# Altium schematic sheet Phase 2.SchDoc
size Tabloid; SheetNumber: 4; SheetTotal: 7
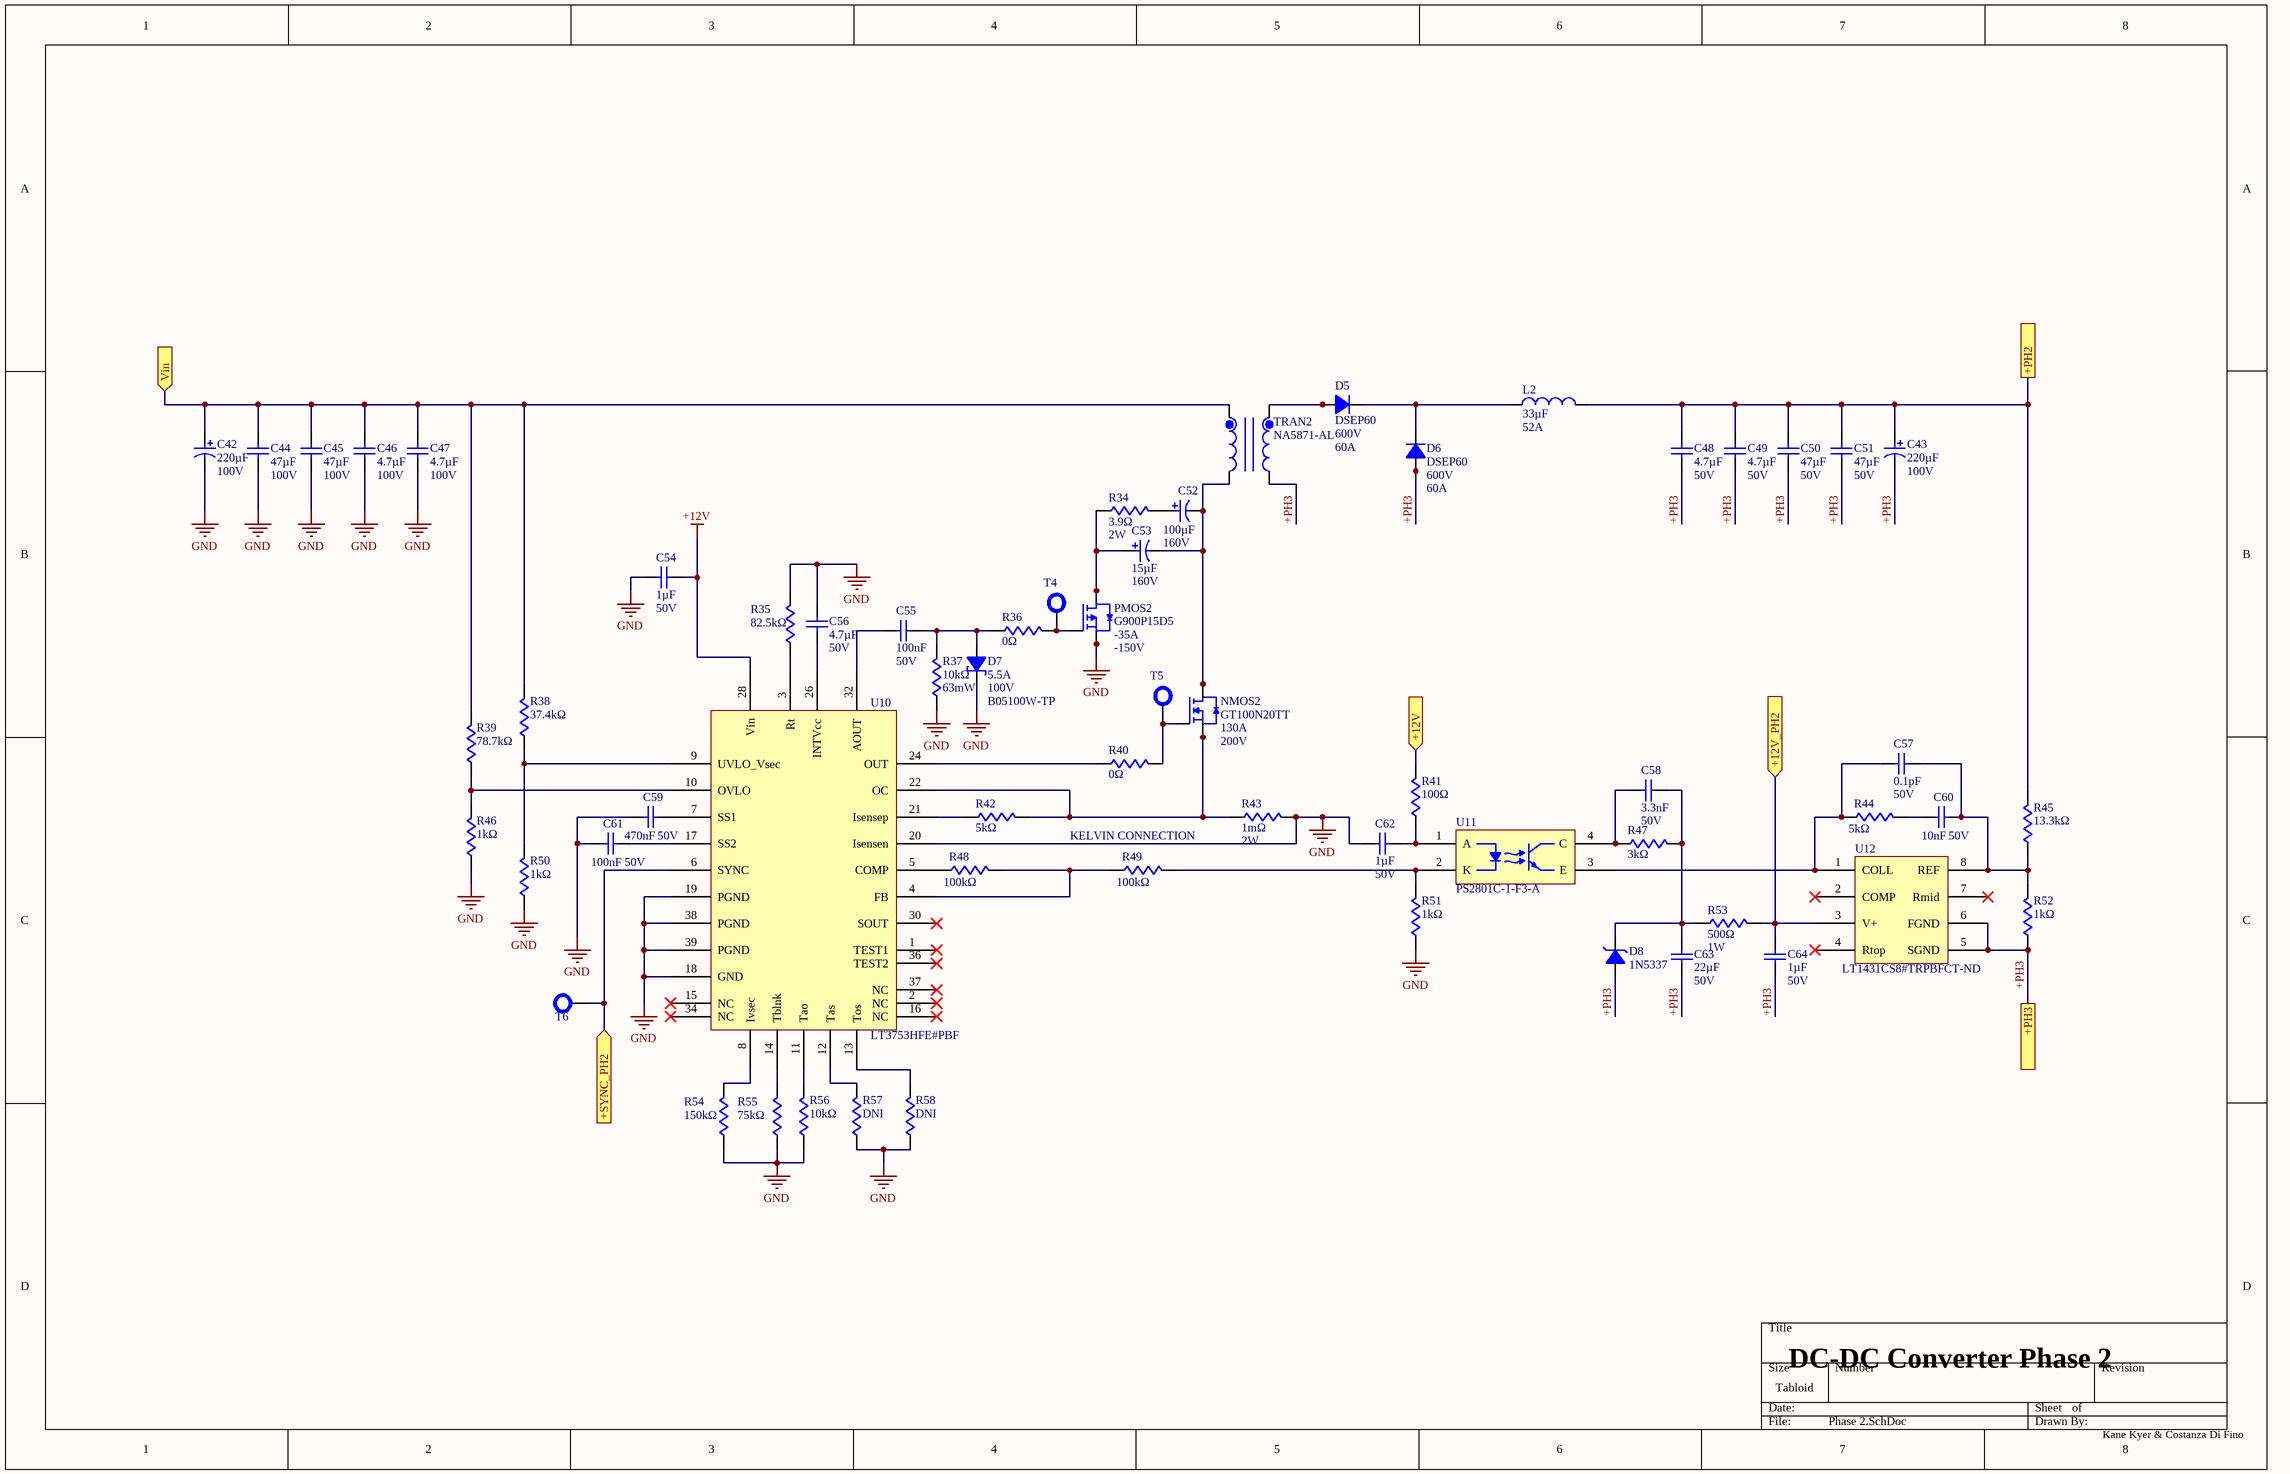
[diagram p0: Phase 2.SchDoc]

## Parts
C42  value 220µF  Voltage Rating: 100V  [C_AEC]  (hidden comment: AFK227M2AR44T-F)
C43  value 220µF  Voltage Rating: 100V  [C_AEC]  (hidden comment: AFK227M2AR44T-F)
C44  value 47µF  Voltage Rating: 100V  [C_CAA573]  (hidden comment: CAA573X7S2A476M640LH)
C45  value 47µF  Voltage Rating: 100V  [C_CAA573]  (hidden comment: CAA573X7S2A476M640LH)
C46  value 4.7µF  Voltage Rating (DC): 100V  [C_1210]  (hidden comment: GMC32X7S475K100NT)
C47  value 4.7µF  Voltage Rating (DC): 100V  [C_1210]  (hidden comment: GMC32X7S475K100NT)
C48  value 4.7µF  Voltage Rating (DC): 50V  [C_1206]  (hidden comment: GMC31X7R475K50NT)
C49  value 4.7µF  Voltage Rating (DC): 50V  [C_1206]  (hidden comment: GMC31X7R475K50NT)
C50  value 47µF  Voltage Rating (DC): 50V  [C_CKG57N]  (hidden comment: CKG57NX7R1H476M500JJ)
C51  value 47µF  Voltage Rating (DC): 50V  [C_CKG57N]  (hidden comment: CKG57NX7R1H476M500JJ)
C52  value 100µF  Voltage Rating (DC): 160V  [UUJ2C101MNJ1MS]  (hidden comment: UUJ2C101MNJ1MS)
C53  value 15µF  Voltage: 160V  [ULT2C150MNL1GS]  (hidden comment: ULT2C150MNL1GS)
C54  value 1µF  Voltage: 50V  [C_0805]  (hidden comment: CL21B105KBFNNNE)
C55  value 100nF  Voltage Rating: 50V  [C_0603]  (hidden comment: C0603C104K5RACTU)
C56  value 4.7µF  Voltage Rating (DC): 50V  [C_1206]  (hidden comment: GMC31X7R475K50NT)
C57  value 0.1pF  Voltage Rating: 50V  [C_0402]  (hidden comment: GJM1555C1HR10WB01D)
C58  value 3.3nF  Voltage Rating: 50V  [C_0603]  (hidden comment: GCM1885C1H332FA16D)
C59  value 470nF  Voltage Rating: 50V  [C_0402]  (hidden comment: GRM155R61H474KE11D)
C60  value 10nF  Voltage Rating: 50V  [C_0603]  (hidden comment: C0603C103K5RACTU)
C61  value 100nF  Voltage Rating: 50V  [C_0603]  (hidden comment: C0603C104K5RACTU)
C62  value 1µF  Voltage: 50V  [C_0805]  (hidden comment: CL21B105KBFNNNE)
C63  value 22µF  Voltage Rating (DC): 50V  [C_2220]  (hidden comment: GMC55X7R226M50NT)
C64  value 1µF  Voltage: 50V  [C_0805]  (hidden comment: CL21B105KBFNNNE)
D5  DSEP60  Vr: 600V  Io: 60A  [D_DSEP60]
D6  DSEP60  Vr: 600V  Io: 60A  [D_DSEP60]
D7  Max Forward Surge Current (Ifsm): 5.5A  Min Breakdown Voltage: 100V  [D_B05100W]  (hidden comment: B05100W-TP)
D8  Supplier Part Number: 1N5337  [D_1N5337]  (hidden comment: 1N5337BRLG)
L2  value 33µF  Irms: 52A  [CPEX4141L-330MC]  (hidden comment: CPEX4141L-330MC)
NMOS2  Id: 130A  Vds: 200V  [GT100N20TT]  (hidden comment: GT100N20TT)
PMOS2  Id: -35A  Vds: -150V  [G900P15]  (hidden comment: G900P15D5)
R34  value 3.9Ω  Power Rating: 2W  [R_SM2W]  (hidden comment: SMW23R9JT)
R35  value 82.5kΩ  [R_0805]  (hidden comment: RMCF0805FT82K5)
R36  value 0Ω  [R_0805]  (hidden comment: CRCW08050000Z0EA)
R37  value 10kΩ  Power Rating: 63mW  [R_0402]  (hidden comment: RM04F1002CT)
R38  value 37.4kΩ  [R_0603]  (hidden comment: RC0603FR-0737K4L)
R39  value 78.7kΩ  [R_0603]  (hidden comment: RC0603FR-0778K7L)
R40  value 0Ω  [R_0805]  (hidden comment: CRCW08050000Z0EA)
R41  value 100Ω  [R_0603]  (hidden comment: RC0603FR-07100RL)
R42  value 5kΩ  [R_0402]  (hidden comment: PNM0402E5001BST1)
R43  value 1mΩ  Power Rating: 2W  [R_2512]  (hidden comment: CRE2512-FZ-R001E-2)
R44  value 5kΩ  [R_0402]  (hidden comment: PNM0402E5001BST1)
R45  value 13.3kΩ  [R_0603]  (hidden comment: RMCF0603FT13K3)
R46  value 1kΩ  [R_0402]  (hidden comment: RM04F1001CT)
R47  value 3kΩ  [C_0402]  (hidden comment: AC0402FR-073KL)
R48  value 100kΩ  [R_0402]  (hidden comment: RM04F1003CT)
R49  value 100kΩ  [R_0402]  (hidden comment: RM04F1003CT)
R50  value 1kΩ  [R_0402]  (hidden comment: RM04F1001CT)
R51  value 1kΩ  [R_0402]  (hidden comment: RM04F1001CT)
R52  value 1kΩ  [R_0402]  (hidden comment: RM04F1001CT)
R53  value 500Ω  Power Rating: 1W  [R_WSC2515]  (hidden comment: WSC2515500R0FEB)
R54  value 150kΩ  [R_0603]  (hidden comment: RC0603FR-07150KL)
R55  value 75kΩ  [R_0603]  (hidden comment: AC0603FR-0775KL)
R56  value 10kΩ  [R_0402]  (hidden comment: RM04F1002CT)
R57  value DNI  [R_0805]  (hidden comment: CRCW08050000Z0EA)
R58  value DNI  [R_0805]  (hidden comment: CRCW08050000Z0EA)
T4  TEST  [TEST_POINT]  (value not drawn)
T5  TEST  [TEST_POINT]  (value not drawn)
T6  TEST  [TEST_POINT]  (value not drawn)
TRAN2  NA5871-AL  [NA5871-AL]
U10  LT3753HFE#PBF  [LT3753]
U11  PS2801C-1-F3-A  [PS2801C]
U12  Supplier Part Number: LT1431CS8#TRPBFCT-ND  [LT1431]  (hidden comment: LT1431CS8#TRPBF)

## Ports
+12V (in, see SHEET_MAP[4B], Externals[2A], Phase 1[4C], Phase 3[4C], Phase 4[4C], Phase 5[4B]), +12V_PH2 (in, see SHEET_MAP[4B], Externals[5B]), +PH2 (see SHEET_MAP[4B], Externals[4B], Phase 1[6C]), +PH3 (see SHEET_MAP[4B], Externals[4C], Phase 3[6B]), +SYNC_PH2 (in, see SHEET_MAP[4B], Externals[3C]), Vin (in, see SHEET_MAP[4B], Externals[1A], Phase 1[1B], Phase 3[1B], Phase 4[1B], Phase 5[1B])

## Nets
+12V: C54.2 U10.28(Vin)
GND: C42.2 C44.1 C45.1 C46.1 C47.1 C54.1 C56.1 C59.1 C61.1 C62.1 D7.1 PMOS2.1(S) PMOS2.2(S) PMOS2.3(S) R35.2 R37.1 R43.2 R46.1 R50.1 R51.1 R54.1 R55.1 R56.1 R57.1 R58.1 U10.18(GND) U10.19(PGND) U10.20(Isensen) U10.38(PGND) U10.39(PGND)
+12V: R41.2 ; port +12V  [a separate net that carries the same name]
+12V_PH2: C64.2 R53.2 U12.3(V+) ; port +12V_PH2
+PH2: C43.1 C48.2 C49.2 C50.2 C51.2 L2.2 R45.2 ; port +PH2
+PH3: C43.2 C48.1 C49.1 C50.1 C51.1 C63.1 C64.1 D6.1(A) D6.3(A) D8.2 R52.1 TRAN2.11 U12.5(SGND) U12.6(FGND) ; port +PH3
+SYNC_PH2: T6.1 U10.6(SYNC) ; port +SYNC_PH2
Vin: C42.1 C44.2 C45.2 C46.2 C47.2 R38.2 R39.2 TRAN2.1 ; port Vin
NetC52_1: C52.1 R34.2
NetC52_2: C52.2 C53.2 NMOS2.9(D) NMOS2.10(D) NMOS2.11(D) NMOS2.12(D) NMOS2.13(D) NMOS2.14(D) NMOS2.15(D) NMOS2.16(D) TRAN2.4
NetC53_1: C53.1 PMOS2.5(D) PMOS2.6(D) PMOS2.7(D) PMOS2.8(D) R34.1
NetC55_1: C55.1 U10.32(AOUT)
NetC55_2: C55.2 D7.2 R36.1 R37.2
NetC56_2: C56.2 U10.26(INTVcc)
NetC57_1: C57.1 R44.1 U11.3(E) U12.1(COLL)
NetC57_2: C57.2 C60.2 R45.1 R52.2 U12.8(REF)
NetC58_1: C58.1 R47.1 U11.4(C)
NetC58_2: C58.2 C63.2 D8.1 R47.2 R53.1
NetC59_2: C59.2 U10.7(SS1)
NetC60_1: C60.1 R44.2
NetC61_2: C61.2 U10.17(SS2)
NetC62_2: C62.2 R41.1 U11.1(A)
NetD5_1: D5.1(A) D5.3(A) TRAN2.6
NetD5_4: D5.4(C) D6.4(C) L2.1
NetNMOS2_1: NMOS2.1(S) NMOS2.2(S) NMOS2.3(S) NMOS2.4(S) NMOS2.5(S) NMOS2.6(S) NMOS2.7(S) R42.2 R43.1 U10.22(OC)
NetNMOS2_8: NMOS2.8(G) R40.2 T5.1
NetPMOS2_4: PMOS2.4(G) R36.2 T4.1
NetR35_1: R35.1 U10.3(Rt)
NetR38_1: R38.1 R50.2 U10.9(UVLO_Vsec)
NetR39_1: R39.1 R46.2 U10.10(OVLO)
NetR40_1: R40.1 U10.24(OUT)
NetR42_1: R42.1 U10.21(Isensep)
NetR48_1: R48.1 U10.5(COMP)
NetR48_2: R48.2 R49.1 U10.4(FB)
NetR49_2: R49.2 R51.2 U11.2(K)
NetR54_2: R54.2 U10.8(Ivsec)
NetR55_2: R55.2 U10.14(Tblnk)
NetR56_2: R56.2 U10.11(Tao)
NetR57_2: R57.2 U10.12(Tas)
NetR58_2: R58.2 U10.13(Tos)

Not connected (* = marked no-connect by the designer): U10 1(TEST1)* 2(NC)* 15(NC)* 16(NC)* 30(SOUT)* 34(NC)* 36(TEST2)* 37(NC)*; U12 2(COMP)* 4(Rtop)* 7(Rmid)*

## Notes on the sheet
- (near R49) KELVIN CONNECTION
- DC-DC Converter Phase 2
- Kane Kyer & Costanza Di Fino

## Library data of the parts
C42 C43 = AFK227M2AR44T-F: Radial Can - SMD ALUMINUM ELECTROLYTIC CAPACITOR AFK 100V 220muF ±20% 0.709Dia 18.00mm; Manufacturer: Cornell Dubilier; Dissipation Factor: 0.07%; ESR (Equivalent Series Resistance): 150mΩ; Leakage Current: 220µA; Life (Hours): 5000hours; Ripple Current: 687.75mA; Ripple Current (AC): 917mA
C44 C45 = CAA573X7S2A476M640LH: Multilayer Ceramic Chip Capacitors, Capacitance=47μF, LxWxT: 6.0x7.5x6.4mm; Manufacturer: TDK; Manufacturer Lifecycle Status: PRODUCTION; Tolerance: 20%
C46 C47 = GMC32X7S475K100NT: Ceramic Capacitor, Multilayer, Ceramic, 100V, 10% +Tol, 10% -Tol, X7S, 22% TC, 4.7uF, Surface Mount, 1210; Manufacturer: Cal-Chip Electronics
C48 C49 C56 = GMC31X7R475K50NT: Ceramic Capacitor, Multilayer, Ceramic, 50V, 10% +Tol, 10% -Tol, X7R, 15% TC, 4.7uF, Surface Mount, 1206; Manufacturer: Cal-Chip Electronics
C50 C51 = CKG57NX7R1H476M500JJ: Ceramic Capacitor, Multilayer, Ceramic, 50V, 20% +Tol, 20% -Tol, X7R, 15% TC, 47uF, Surface Mount, 2420; Manufacturer: TDK; Manufacturer Lifecycle Status: PRODUCTION
C52 = UUJ2C101MNJ1MS: Aluminum Electrolytic Capacitors 100 F 160 V Radial, SMD 5000 Hrs 105C; Manufacturer: Nichicon; Leakage Current: 740µA; Ripple Current: 380mA
C53 = ULT2C150MNL1GS: Radial Can - SMD ALUMINUM ELECTROLYTIC CAPACITOR ULT 160V 15muF ±20% 0.315Dia 8.00mm; Manufacturer: Nichicon; Leakage Current: 196µA; Life (Hours): 2000hours; Polarity: Polar; Ripple Current: 45mA
C54 C62 C64 = CL21B105KBFNNNE: 50V 1uF X7R ±10% 0805 Multilayer Ceramic Capacitors MLCC - SMD/SMT ROHS; Manufacturer: Samsung Electro-Mechanics
C55 C61 = C0603C104K5RACTU: 50V 100nF X7R ±10% 0603 Multilayer Ceramic Capacitors MLCC - SMD/SMT ROHS; Manufacturer: KEMET; Dissipation Factor: 2.5%; Temperature Coefficient: 30ppm/°C
C57 = GJM1555C1HR10WB01D: Multilayer Ceramic Capacitor, 0.1 pF, 50 V, ± 0.05pF, C0G (NP0), 0402 [1005 Metric]; Manufacturer: Murata; Manufacturer Lifecycle Status: IN PRODUCTION; Temperature Coefficient: 30ppm/°C
C58 = GCM1885C1H332FA16D: 50V 3.3nF C0G ±1% 0603 Multilayer Ceramic Capacitors MLCC - SMD/SMT ROHS; Manufacturer: Murata; Manufacturer Lifecycle Status: IN PRODUCTION; Temperature Coefficient: 30ppm/°C
C59 = GRM155R61H474KE11D: 50V 470nF X5R ±10% 0402 Multilayer Ceramic Capacitors MLCC - SMD/SMT ROHS; Manufacturer: Murata; Manufacturer Lifecycle Status: IN PRODUCTION
C60 = C0603C103K5RACTU: Capacitor, Multilayer, Ceramic, 50V, 10%, X7R, 15% Tc, 0.01Uf, Surface Mount, 0603; Manufacturer: KEMET; Dissipation Factor: 2.5%; Temperature Coefficient: 30ppm/°C
C63 = GMC55X7R226M50NT: Ceramic Capacitor, Multilayer, Ceramic, 50V, 20% +Tol, 20% -Tol, X7R, 15% TC, 22uF, Surface Mount, 2220; Manufacturer: Cal-Chip Electronics
D5 D6 = DSEP60-06AZ-TRL: Power Diode Discretes-FRED TO-; Manufacturer: IXYS
D7 = B05100W-TP: Rectifier Diode, Schottky, 1 Phase, 1 Element, 0.5A, 100V V(RRM), Silicon; Manufacturer: MCC; Forward Voltage: 850mV; Max Output current: 500mA; Number of Elements: 1; Peak Reverse Current: 1µA
D8 = 1N5337BRLG: Zener Diode Single 4.7V 5% 2Ohm 5000mW 2-Pin Case 017AA-01 T/R / DIODE ZENER 4.7V 5W AXIAL; Manufacturer: onsemi; Manufacturer Lifecycle Status: ACTIVE; Forward Voltage: 1.2V; Impedance: 2Ω; Max Reverse Leakage Current: 5µA; Number of Elements: 1; Polarity: Unidirectional; Test Current: 260mA
L2 = CPEX4141L-330MC: Fixed Ind 33UH 52A 1.88 Mohm Th; Manufacturer: Codaca
NMOS2 = GT100N20TT: Mosfet N-ch 200V 130A 280W Tolt; Manufacturer: GoFord
PMOS2 = G900P15D5: P-150V, -60A, RD(max) Less Than 80mOhm at -10V, VTH -1V to -4V, DFN5x6-8L; Manufacturer: GoFord; Manufacturer Lifecycle Status: ACTIVE
R34 = SMW23R9JT: SM Series 3.9 Ohm ±5 % 2 W ±200 ppm/°C Surface Mount Wirewound Resistor; Manufacturer: TE Connectivity; Manufacturer Lifecycle Status: ACTIVE; Insulation Resistance: 10GΩ; Number of Resistors: 1; Operating Supply Voltage: 300V; Tolerance: 5%
R35 = RMCF0805FT82K5: Res Thick Film 0805 82.5K Ohm 1% 1/8W ±100ppm/°C Molded SMD SMD Paper T/R; Manufacturer: Stackpole Electronics; Max Power Dissipation: 125mW; Voltage Rating: 150V
R36 R40 R57 R58 = CRCW08050000Z0EA: Zero Ohm Resistor, Jumper, 0805 [2012 Metric], Thick Film, 125 mW, 2.5 A, Surface Mount Device; Manufacturer: Vishay; Manufacturer Package Identifier: CRCW0805-e3; Power Dissipation: 125mW; Temperature Coefficient: 100ppm/°C; Tolerance: 1%; Voltage Rating: 150V
R37 = RM04F1002CT: Fixed Resistor, Metal Glaze/thick Film, 0.0625W, 10000ohm, 50V, 1% +/-Tol, Surface Mount, 0402; Manufacturer: Cal-Chip Electronics; Power Dissipation: 62.5mW; Temperature Coefficient: 100ppm/°C
R38 = RC0603FR-0737K4L: 100mW Thick Film Resistors 75V ±100ppm/℃ ±1% 37.4kΩ 0603 Chip Resistor - Surface Mount ROHS; Manufacturer: Yageo Group; Temperature Coefficient: 100ppm/°C; Voltage Rating (DC): 50V
R39 = RC0603FR-0778K7L: Res Thick Film 0603 78.7K Ohm 1% 0.1W(1/10W) ±100ppm/C Pad SMD T/R; Manufacturer: Yageo Group; Power Dissipation: 100mW; Temperature Coefficient: 100ppm/°C; Voltage Rating: 75V; Voltage Rating (DC): 50V
R41 = RC0603FR-07100RL: Yageo RC0603FR-07100RL 0603 SMD Resistor 100 Ohm thin film chip resistor; Manufacturer: Yageo Group; Power Dissipation: 100mW; Temperature Coefficient: 100ppm/°C; Tolerance: 1%; Voltage Rating: 75V; Voltage Rating (DC): 50V
R42 R44 = PNM0402E5001BST1: Res Thin Film 0402 5K Ohm 0.1% 0.05W(1/20W) +/-25ppm/C Sulfur Resistant Pad SMD Medical T/R; Manufacturer: Vishay; Power Dissipation: 50mW; Temperature Coefficient: 25ppm/°C; Working Voltage: 75V
R43 = CRE2512-FZ-R001E-2: Res Thick Film 2512 1m Ohm 1% 2W ±75ppm/°C Molded SMD Embossed T/R; Manufacturer: Bourns; Temperature Coefficient: 50ppm/°C
R45 = RMCF0603FT13K3: Res Thick Film 0603 13.3K Ohm 1% 0.1W(1/10W) ±100ppm/C Pad SMD Automotive T/R; Manufacturer: Stackpole Electronics; Power Dissipation: 100mW; Temperature Coefficient: 100ppm/°C; Voltage Rating: 75V
R46 R50-R52 = RM04F1001CT: 62.5mW Thick Film Resistors ±100ppm/℃ ±1% 1kΩ 0402 Chip Resistor - Surface Mount ROHS; Manufacturer: Cal-Chip Electronics; Temperature Coefficient: 100ppm/°C; Working Voltage: 50V
R47 = AC0402FR-073KL: Res Thick Film 0402 3K Ohm 1% 0.063W(1/16W) ±100ppm/C Pad SMD Automotive T/R; Manufacturer: Yageo Group; Max Power Dissipation: 63mW; Power Dissipation: 62.5mW; Temperature Coefficient: 100ppm/°C; Voltage Rating: 50V
R48 R49 = RM04F1003CT: Fixed Resistor, Metal Glaze/thick Film, 0.0625W, 100000ohm, 50V, 1% +/-Tol, Surface Mount, 0402; Manufacturer: Cal-Chip Electronics; Power Dissipation: 62.5mW; Temperature Coefficient: 100ppm/°C
R53 = WSC2515500R0FEB: Fixed Resistor, Wire Wound, 1W, 500ohm, 22.3607V, 1% +/-Tol, 20ppm/Cel, Surface Mount, 2515; Manufacturer: Vishay; Temperature Coefficient: 20ppm/°C
R54 = RC0603FR-07150KL: 100mW Thick Film Resistors 75V ±100ppm/℃ ±1% 150kΩ 0603 Chip Resistor - Surface Mount ROHS; Manufacturer: Yageo Group; Temperature Coefficient: 100ppm/°C; Voltage Rating (AC): 50V
R55 = AC0603FR-0775KL: Res Thick Film 0603 75K Ohm 1% 0.1W(1/10W) ±100ppm/C Pad SMD T/R Automotive AEC-Q200; Manufacturer: Yageo Group; Max Power Dissipation: 100mW; Temperature Coefficient: 100ppm/°C; Voltage Rating: 75V
R56 = RM04F1002CT: Fixed Resistor, Metal Glaze/thick Film, 0.0625W, 10000ohm, 50V, 1% +/-Tol, Surface Mount, 0402; Manufacturer: Cal-Chip Electronics; Power Dissipation: 62.5mW; Power Rating: 63mW; Temperature Coefficient: 100ppm/°C
TRAN2 = NA5871-AL: Transformer, planar, for TI UCC28950, SMT, RoHS; Manufacturer: Coilcraft; Max Supply Voltage: 60V; Min Input Voltage: 38V; Power Rating: 800W
U10 = LT3753HFE#PBF: 500kHz 8.5V~100V Buck-boost type 1 TSSOP-38-EP-4.4mm DC-DC Controllers ROHS; Manufacturer: Analog Devices; Manufacturer Lifecycle Status: PRODUCTION; Clock Sync: Yes; Max Supply Voltage: 100V; Min Supply Voltage: 8.5V; Nominal Supply Voltage: 12V; Number of Output Phases: 1; Topology: Forward Converter
U11 = PS2801C-1-F3-A: Optocoupler DC-IN 1-CH Transistor DC-OUT 4-Pin SSOP T/R; Manufacturer: Renesas; Manufacturer Lifecycle Status: ACTIVE; Collector Emitter Breakdown Voltage: 80V; Collector Emitter Saturation Voltage: 300mV; Current Transfer Ratio: 50%; Dark Current: 100nA; Forward Current: 30mA; Forward Voltage: 1.4V; Input Current: 5mA; Isolation Voltage: 2.5kV; Max Power Dissipation: 120mW; Number of Elements: 1; Reverse Breakdown Voltage: 6V; Target Application: PLC\, Hybrid IC\, Power supply\, OA\, Measuring instrument\, Modem\, Communication devices
U12 = LT1431CS8#TRPBF: V-Ref Adjustable 2.5V to 36V 100mA 8-Pin SOIC N T/R; Manufacturer: Analog Devices; Manufacturer Lifecycle Status: PRODUCTION; Cathode Current: 1mA; Reference Type: Shunt; Temperature Coefficient: 30ppm/°C; Tolerance: 0.4%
